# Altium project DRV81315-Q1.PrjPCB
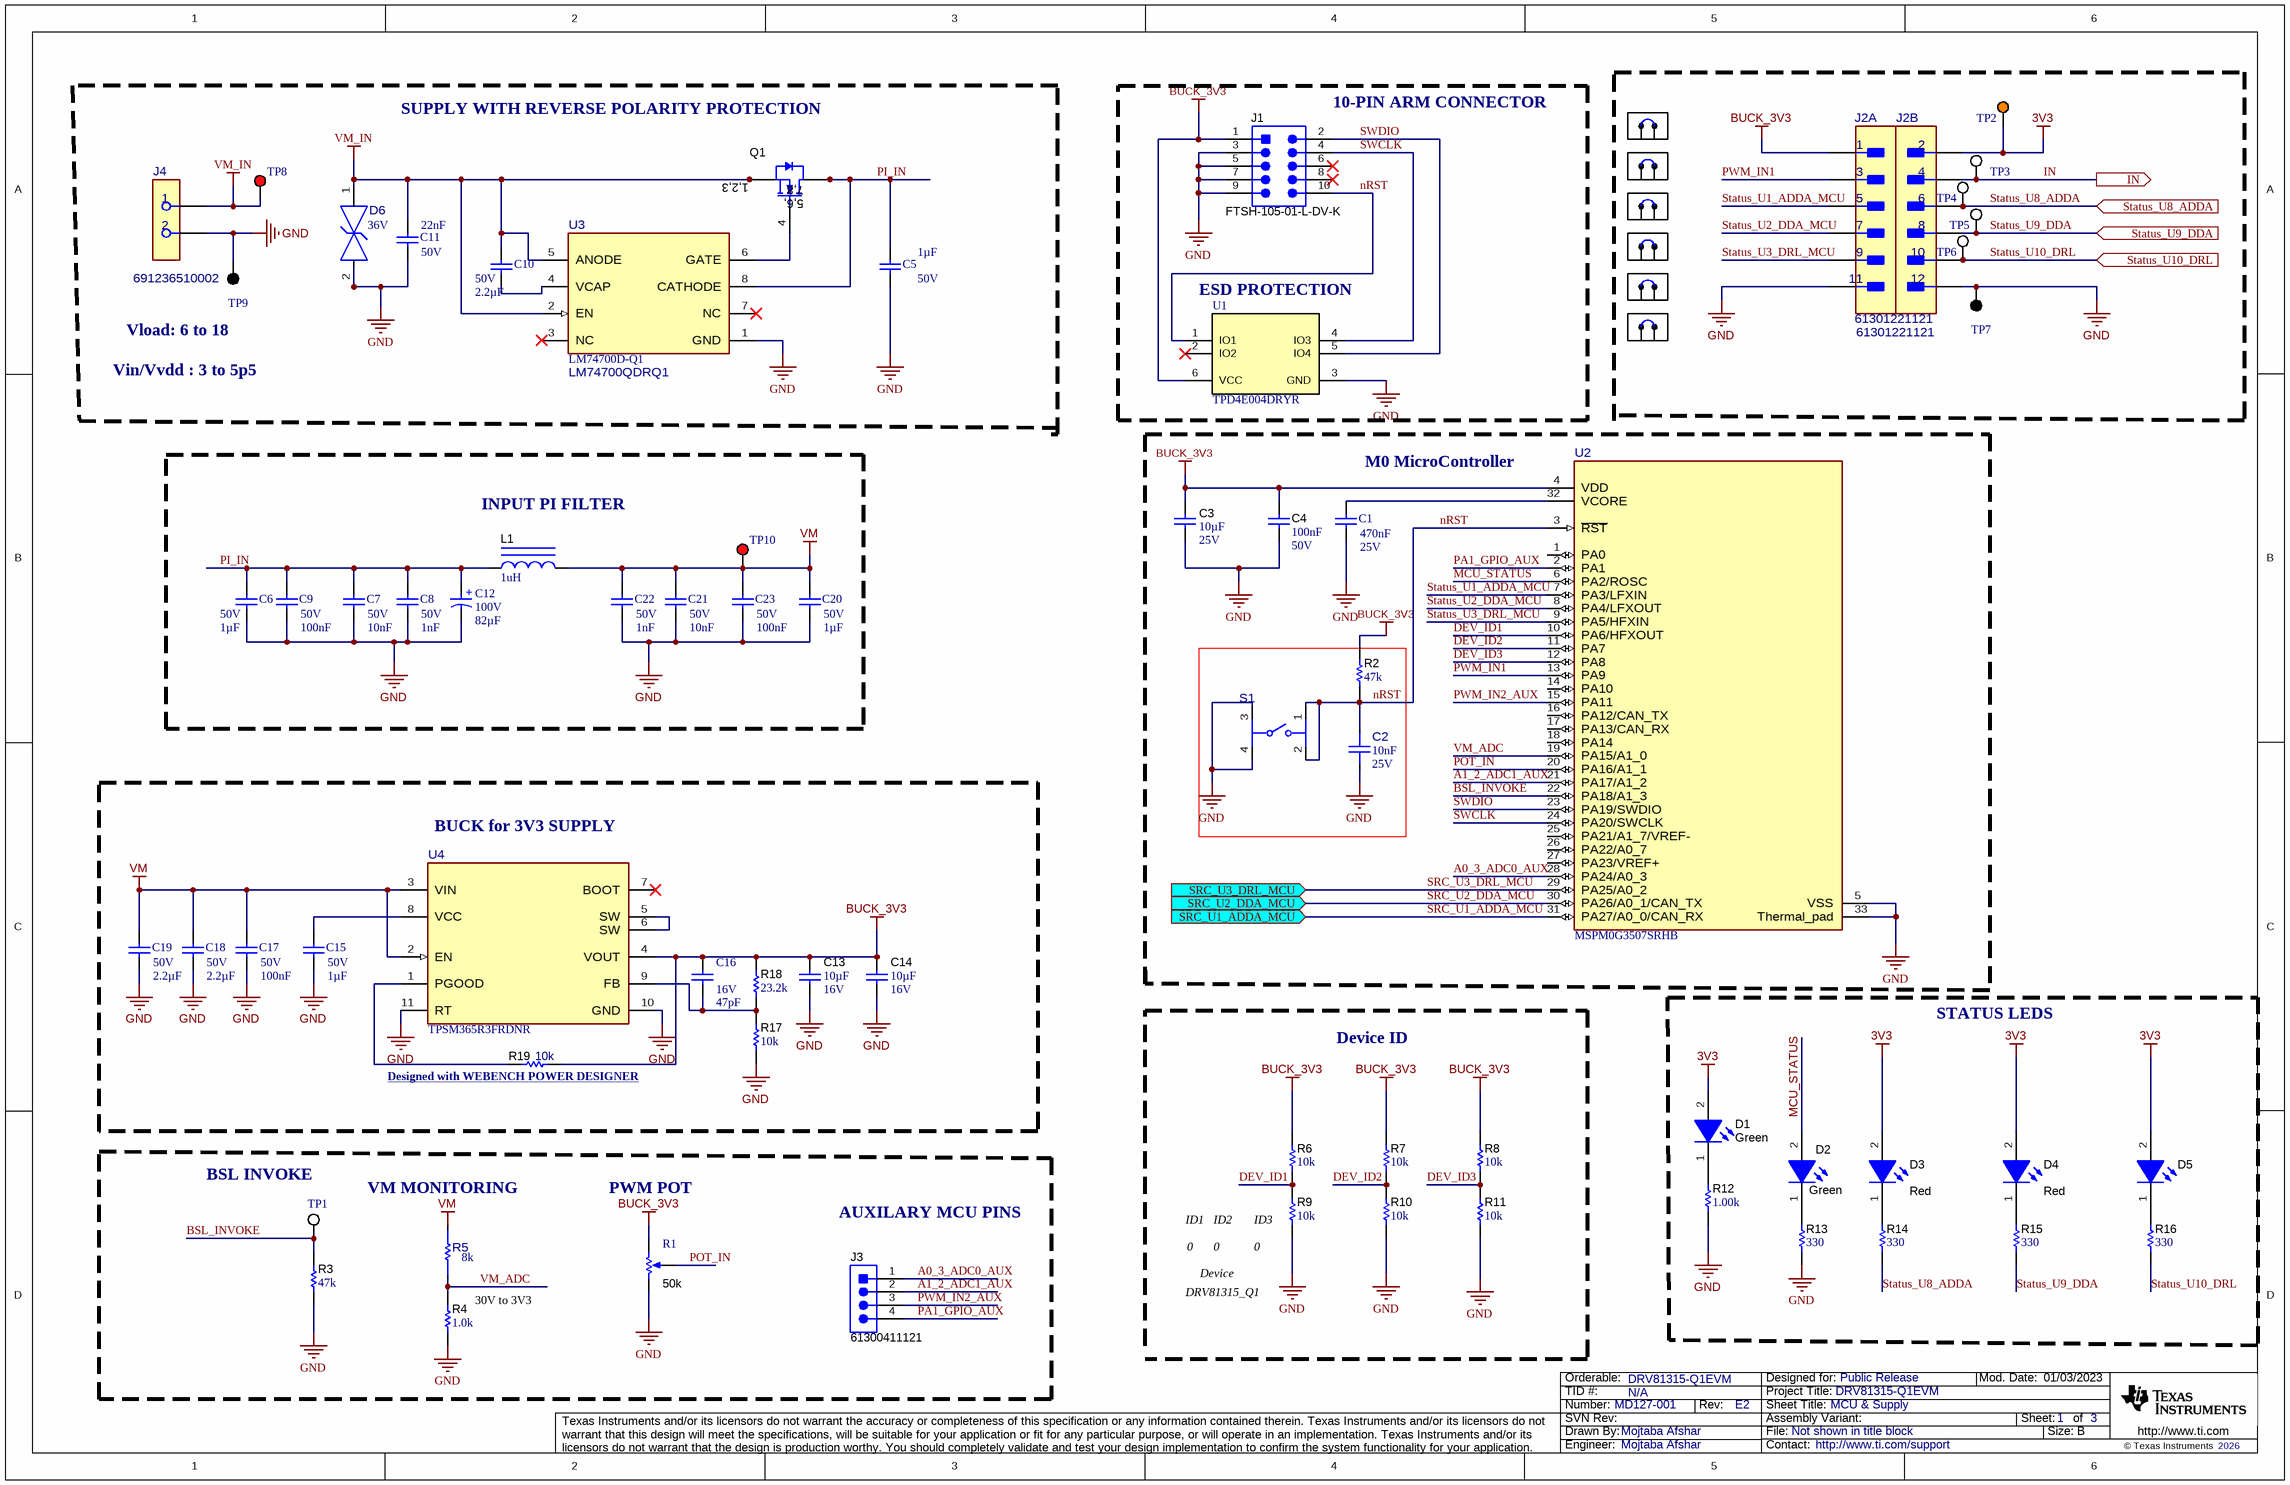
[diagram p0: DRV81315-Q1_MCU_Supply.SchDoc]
CopyrightYear: 2026; EVM_Orderable: DRV81315-Q1EVM; PCB_Layout: Mojtaba Afshar; PCB_Rev: E2; PRJ_Customer: Public Release; PRJ_Engineer: Mojtaba Afshar; PRJ_Number: MD127-001; PRJ_Title: DRV81315-Q1EVM; SCH_Rev: E2; TechSupport: http://www.ti.com/support; TID: N/A
3 sheets, 153 parts. Net scope: flat (ports and power ports of the same name join across sheets).
Board file: MD127_DRV81315_031026.PcbDoc
Sheets:
  DRV81315-Q1_MCU_Supply.SchDoc
  DRV81315AQ1_ICs.SchDoc
  DRV81315-Q1_HW.SchDoc

## Sheet DRV81315-Q1_MCU_Supply.SchDoc: MCU & Supply
size 431 x 279 mm; Date: Not shown in title block; ApprovedBy: Not shown in title block; CheckedBy: Not shown in title block; Author: Not shown in title block; CompanyName: Not shown in title block; DrawnBy: Mojtaba Afshar; Engineer: Not shown in title block; Organization: Not shown in title block; Address1: Not shown in title block; Address2: Not shown in title block; Address3: Not shown in title block; Address4: Not shown in title block; DocumentNumber: 1; Revision: Use project parameter SCH_Rev; SheetNumber: 1; SheetTotal: 3; PageSetup: Record=PageOptions¦CenterHorizontal=True¦CenterVertical=True¦PrintScale=1.00¦XCorrection=1.00¦YCorrection=1.00¦PrintKind=0¦BorderSize=5000000¦LeftOffset=0¦BottomOffset=0¦Orientation=2¦PaperLength=1000¦PaperWidth=1000¦Scale=100¦PaperSource=15¦PrintQuality=600¦MediaType=1¦DitherType=10¦PaperKind=Letter¦PrintScaleMode=1

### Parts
C1  value 470nF  Rated Voltage (DC): 25V  [WCAP-CSGP_0603_L1.6W0.8H0.8_Reflow]  (hidden comment: 885012206075R)
C2  Cap_F: 10nF  VDC_V: 25V  [FP-885012206065_0603-MFG]  (hidden comment: 885012206065)
C3  Cap_F: 10µF  VDC_V: 25V  [0603]  (hidden comment: GRM188R61E106KA73D)
C4  Cap_F: 100nF  VDC_V: 50V  [0603]  (hidden comment: 885012206095)
C5  value 1µF  Rated Voltage (DC): 50V  [WCAP-CSGP_1206_L3.2W1.6H1.6]  (hidden comment: 885012208093)
C6  value 1µF  Rated Voltage (DC): 50V  [WCAP-CSGP_1206_L3.2W1.6H1.6]  (hidden comment: 885012208093)
C7  value 10nF  Rated Voltage (DC): 50V  [WCAP-CSGP_0402_L1W0.5H0.5]  (hidden comment: 885012205067)
C8  value 1nF  Rated Voltage (DC): 50V  [WCAP-CSGP_0402_L1W0.5H0.5]  (hidden comment: 885012205061)
C9  value 100nF  Rated Voltage (DC): 50V  [WCAP-CSGP_0603_L1.6W0.8H0.8_Reflow]  (hidden comment: 885012206095)
C10  value 2.2µF  Rated Voltage (DC): 50V  [WCAP-CSGP_1812_L4.5W3.2H2.5]  (hidden comment: 885012210032)
C11  value 22nF  Rated Voltage (DC): 50V  [WCAP-CSGP_0603_L1.6W0.8H0.8_Reflow]  (hidden comment: 885012206091)
C12  value 82µF  Rated Voltage (DC): 100V  [WCAP-ATUL_D10H20]  (hidden comment: 860040875004)
C13  VDC_V: 16V  ValueDisplayed: 10µF  [0805_150]  (hidden comment: 885012107014)
C14  VDC_V: 16V  ValueDisplayed: 10µF  [0805_150]  (hidden comment: 885012107014)
C15  value 1µF  Rated Voltage (DC): 50V  [WCAP-CSGP_1206_L3.2W1.6H1.6]  (hidden comment: 885012208093)
C16  value 47pF  Rated Voltage (DC): 16V  [WCAP-CSGP_0402_L1W0.5H0.5]  (hidden comment: 885012005029)
C17  value 100nF  Rated Voltage (DC): 50V  [WCAP-CSGP_0603_L1.6W0.8H0.8_Reflow]  (hidden comment: 885012206095)
C18  value 2.2µF  Rated Voltage (DC): 50V  [WCAP-CSGP_1812_L4.5W3.2H2.5]  (hidden comment: 885012210032)
C19  value 2.2µF  Rated Voltage (DC): 50V  [WCAP-CSGP_1812_L4.5W3.2H2.5]  (hidden comment: 885012210032)
C20  value 1µF  Rated Voltage (DC): 50V  [WCAP-CSGP_1206_L3.2W1.6H1.6]  (hidden comment: 885012208093)
C21  value 10nF  Rated Voltage (DC): 50V  [WCAP-CSGP_0402_L1W0.5H0.5]  (hidden comment: 885012205067)
C22  value 1nF  Rated Voltage (DC): 50V  [WCAP-CSGP_0402_L1W0.5H0.5]  (hidden comment: 885012205061)
C23  value 100nF  Rated Voltage (DC): 50V  [WCAP-CSGP_0603_L1.6W0.8H0.8_Reflow]  (hidden comment: 885012206095)
D1  value Green  [WL-SMCW_GREEN]  (hidden comment: 150060VS75000)
D2  value Green  [WL-SMCW_GREEN]  (hidden comment: 150060VS75000)
D3  value Red  [WL-SMCW_RED]  (hidden comment: 150060RS75000)
D4  value Red  [WL-SMCW_RED]  (hidden comment: 150060RS75000)
D5  150060RS75000  [WL-SMCW_RED]  (value not drawn)
D6  VRWM: 36V  [FP-SMBJ36CA-13-F_SMB-MFG]  (hidden comment: SMBJ36CA-13-F)
J1  FTSH-105-01-L-DV-K  [Samtec_FTSH-105-01-x-DV-K]
J2  61301221121  [FP-61301221121_HDR12-MFG]  (parts A,B of 2)
J3  61300411121  [WURTH_61300411121]
J4  691236510002  [FP-691236510002_HHR2-MFG]
L1  ValueDisplayed: 1uH  [WE-LHMI_1335]  (hidden comment: 74437377010)
Q1  CSD19502Q5B  [DNK0008A]  (value not drawn)
R1  value 50k  [Bourns_3352T]  (hidden comment: 3352T-1-503LF)
R2  ValueDisplayed: 47k  [0402]  (hidden comment: CRCW040247K0JNED)
R3  ValueDisplayed: 47k  [0402]  (hidden comment: CRCW040247K0JNED)
R4  ValueDisplayed: 1.0k  [0603]  (hidden comment: RC0603JR-071KL)
R5  value 8k  [FP-RT0603BRE078KL_0603-MFG]  (hidden comment: RT0603BRE078KL)
R6  ValueDisplayed: 10k  [0603L]  (hidden comment: RC0603JR-0710KL)
R7  ValueDisplayed: 10k  [0603L]  (hidden comment: RC0603JR-0710KL)
R8  ValueDisplayed: 10k  [0603L]  (hidden comment: RC0603JR-0710KL)
R9  ValueDisplayed: 10k  [0603L]  (hidden comment: RC0603JR-0710KL)
R10  ValueDisplayed: 10k  [0603L]  (hidden comment: RC0603JR-0710KL)
R11  ValueDisplayed: 10k  [0603L]  (hidden comment: RC0603JR-0710KL)
R12  ValueDisplayed: 1.00k  [0603]  (hidden comment: RC0603FR-071KL)
R13  ValueDisplayed: 330  [0603]  (hidden comment: RC0603JR-07330RL)
R14  ValueDisplayed: 330  [0603]  (hidden comment: RC0603JR-07330RL)
R15  ValueDisplayed: 330  [0603]  (hidden comment: RC0603JR-07330RL)
R16  ValueDisplayed: 330  [0603]  (hidden comment: RC0603JR-07330RL)
R17  ValueDisplayed: 10k  [0603L]  (hidden comment: RC0603JR-0710KL)
R18  ValueDisplayed: 23.2k  [0603]  (hidden comment: RC0603FR-0723K2L)
R19  ValueDisplayed: 10k  [0603L]  (hidden comment: RC0603JR-0710KL)
S1  430481025816  [FP-430481025816_SMT_SW_6MM2_6MM2-MFG]  (value not drawn)
SH1-J2  60900213421  [Wurth_60900213421]  (value not drawn)
SH2-J2  60900213421  [Wurth_60900213421]  (value not drawn)
SH3-J2  60900213421  [Wurth_60900213421]  (value not drawn)
SH4-J2  60900213421  [Wurth_60900213421]  (value not drawn)
SH5-J2  60900213421  [Wurth_60900213421]  (value not drawn)
SH6-J2  60900213421  [Wurth_60900213421]  (value not drawn)
TP1  5002  [Keystone5002]  (value not drawn)
TP2  5013  [Keystone5013]  (value not drawn)
TP3  5012  [Keystone5012]  (value not drawn)
TP4  5012  [Keystone5012]  (value not drawn)
TP5  5012  [Keystone5012]  (value not drawn)
TP6  5012  [Keystone5012]  (value not drawn)
TP7  5011  [Keystone5011]  (value not drawn)
TP8  5010  [Keystone5010]  (value not drawn)
TP9  5011  [Keystone5011]  (value not drawn)
TP10  5010  [Keystone5010]  (value not drawn)
U1  TPD4E004DRYR  [DRY0006A]
U2  MSPM0G3507SRHB  [RHB0032E-MFG]
U3  LM74700QDRQ1  PartNumber: LM74700D-Q1  [D0008A-MFG]
U4  TPSM365R3FRDNR  [RDN0011A-MFG]

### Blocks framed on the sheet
INPUT PI FILTER: C6-C9 C12 C20-C23 L1 TP10
BUCK for 3V3 SUPPLY: C13-C19 R17-R19 U4
STATUS LEDS: D1-D5 R12-R16

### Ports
IN (out), SRC_U1_ADDA_MCU (in), SRC_U2_DDA_MCU (in), SRC_U3_DRL_MCU (in), Status_U8_ADDA (in), Status_U9_DDA (in), Status_U10_DRL (in)

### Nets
3V3: D1.2(A) D3.2(A) D4.2(A) D5.2(A) J2.2 TP2.1
BUCK_3V3: C3.1 C4.1 C13.1 C14.1 C16.2 J1.1 J2.1 R1.1(CCW) R2.2 R6.1 R7.1 R8.1 R18.2 R19.2 U1.6(VCC) U2.4(VDD) U4.4(VOUT)
GND: C1.1 C2.2 C3.2 C4.2 C5.1 C6.1 C7.1 C8.1 C9.1 C11.1 C12.2(N) C13.2 C14.2 C15.1 C17.1 C18.1 C19.1 C20.1 C21.1 C22.1 C23.1 D6.2 J1.3 J1.5 J1.7 J1.9 J2.11 J2.12 J4.2 R1.3(CW) R3.1 R4.1 R9.2 R10.2 R11.2 R12.1 R13.1 R17.1 S1.3 S1.4 TP7.1 TP9.1 U1.3(GND) U2.5(VSS) U2.33(Thermal_pad) U3.1(GND) U4.10(GND) U4.11(RT)
VM: C17.2 C18.2 C19.2 C20.2 C21.2 C22.2 C23.2 L1.2 R5.2 TP10.1 U4.2(EN) U4.3(VIN)
VM_IN: C10.2 C11.2 D6.1 J4.1 Q1.1(S) Q1.2(S) Q1.3(S) TP8.1 U3.2(EN) U3.5(ANODE)
A0_3_ADC0_AUX: J3.1 U2.28(PA24/A0_3)
A1_2_ADC1_AUX: J3.2 U2.21(PA17/A1_2)
BSL_INVOKE: R3.2 TP1.1 U2.22(PA18/A1_3)
DEV_ID1: R6.2 R9.1 U2.10(PA6/HFXOUT)
DEV_ID2: R7.2 R10.1 U2.11(PA7)
DEV_ID3: R8.2 R11.1 U2.12(PA8)
IN: J2.4 TP3.1 ; port IN
MCU_STATUS: D2.2(A) U2.6(PA2/ROSC)
nRST: C2.1 J1.10 R2.1 S1.1 S1.2 U1.1(IO1) U2.3(~{RST})
PA1_GPIO_AUX: J3.4 U2.2(PA1)
PI_IN: C5.2 C6.2 C7.2 C8.2 C9.2 C12.1(P) L1.1 Q1.5(D) Q1.6(D) Q1.7(D) Q1.8(D) Q1.9(D) U3.8(CATHODE)
POT_IN: R1.2(WIPER) U2.20(PA16/A1_1)
PWM_IN1: J2.3 U2.13(PA9)
PWM_IN2_AUX: J3.3 U2.15(PA11)
SRC_U1_ADDA_MCU: U2.31(PA27/A0_0/CAN_RX) ; port SRC_U1_ADDA_MCU
SRC_U2_DDA_MCU: U2.30(PA26/A0_1/CAN_TX) ; port SRC_U2_DDA_MCU
SRC_U3_DRL_MCU: U2.29(PA25/A0_2) ; port SRC_U3_DRL_MCU
Status_U1_ADDA_MCU: J2.5 U2.7(PA3/LFXIN)
Status_U2_DDA_MCU: J2.7 U2.8(PA4/LFXOUT)
Status_U3_DRL_MCU: J2.9 U2.9(PA5/HFXIN)
Status_U8_ADDA: J2.6 R14.1 TP4.1 ; port Status_U8_ADDA
Status_U9_DDA: J2.8 R15.1 TP5.1 ; port Status_U9_DDA
Status_U10_DRL: J2.10 R16.1 TP6.1 ; port Status_U10_DRL
SWCLK: J1.4 U1.4(IO3) U2.24(PA20/SWCLK)
SWDIO: J1.2 U1.5(IO4) U2.23(PA19/SWDIO)
VM_ADC: R4.2 R5.1 U2.19(PA15/A1_0)
NetC1_2: C1.2 U2.32(VCORE)
NetC10_1: C10.1 U3.4(VCAP)
NetC15_2: C15.2 U4.8(VCC)
NetC16_1: C16.1 R17.2 R18.1 U4.9(FB)
NetD1_1: D1.1(K) R12.2
NetD2_1: D2.1(K) R13.2
NetD3_1: D3.1(K) R14.2
NetD4_1: D4.1(K) R15.2
NetD5_1: D5.1(K) R16.2
NetQ1_4: Q1.4(G) U3.6(GATE)
NetR19_1: R19.1 U4.1(PGOOD)
NetU4_5: U4.5(SW) U4.6(SW)

Not connected (* = marked no-connect by the designer): J1 6* 8*; U1 2(IO2)*; U2 1(PA0) 14(PA10) 16(PA12/CAN_TX) 17(PA13/CAN_RX) 18(PA14) 25(PA21/A1_7/VREF-) 26(PA22/A0_7) 27(PA23/VREF+); U3 3(NC)* 7(NC)*; U4 7(BOOT)*

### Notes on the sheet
- SUPPLY WITH REVERSE POLARITY PROTECTION
- (near J1) 10-PIN ARM CONNECTOR
- (near U1) ESD PROTECTION
- (near TP9) Vload: 6 to 18
- Vin/Vvdd : 3 to 5p5
- M0 MicroController
- Device ID
- (near R19) Designed with WEBENCH POWER DESIGNER <https://webench.ti.com/power-designer/switching-regulator/customize/4?VinMin=4.5&VinMax=65&O1V=3.3&O1I=0.3&base_pn=TPSM365R3F&AppType=None&Flavor=None&op_TA=30&origin=pf_panel&lang_chosen=en-US&optfactor=3&Topology=Buck&flavor=None&VoltageOption=None>
- (near TP1) BSL INVOKE
- (near R5) VM MONITORING
- PWM POT
- AUXILARY MCU PINS
- ID1
- ID2
- (near R9) ID3
- 30V to 3V3
- DRV81315_Q1
- 0
- Device
- (near R9) 0

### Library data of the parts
C1 = CMP-0119380-1: WCAP-CSGP Multilayer Ceramic Chip Capacitor, General Purpose, size 0603, X7R Class II, 470nF, 25VDC; Manufacturer: Wurth Elektronik; Capacitance Tolerance: +/-10%; Case/Size Code: 0603; Dissipation Factor: 10%; Insulation Resistance: 1.1GOhm; Technical Reference: X7R0603474K025DFCT20000
C2 = CMP-0120893-1: 10000 pF ±10% 25V Ceramic Capacitor X7R 0603 (1608 Metric); Manufacturer: Wurth Electronics; AEC Qualified: No; SizeZ_mm: 0.87mm; TempCo: 15%; Value: 10nF
C3 = CMP-0860569-1: CAP, CERM, 10 µF, 25 V,+/- 10%, X5R, 0603; Manufacturer: MuRata; TaMin_C: -55°C; Polarized: N; SizeAreaWB_mm2: 4.68; U/M: EA; Value: 10uF; TaMax_C: 85°C; SizeZ_mm: 1; SizeX_mm: 1.6; SizeY_mm: 0.8; SizeArea_mm2: 1.28; AEC Category: Q200
C4 = CMP-0006837-4: CAP, CERM, 0.1 uF, 50 V, +/- 10%, X7R, 0603; Manufacturer: Wurth Elektronik; TaMin_C: -55°C; Polarized: N; SizeAreaWB_mm2: 4.68; Value1: Unknown; U/M: EA; Value: 0.1uF; TaMax_C: 125°C; SizeZ_mm: 1; SizeX_mm: 1.6; SizeY_mm: 0.8; SizeArea_mm2: 1.28; AEC Category: Q200
C5 C6 C15 C20 = CMP-0119636-1: WCAP-CSGP Multilayer Ceramic Chip Capacitor, General Purpose, size 1206, X7R, 1µF, 50VDC; Manufacturer: Wurth Elektronik; Capacitance Tolerance: +/-10%; Case/Size Code: 1206; Dissipation Factor: 3%; Insulation Resistance: 0.5GOhm; Technical Reference: X7R1206105K050DFCT10000
C7 C21 = CMP-0119297-1: WCAP-CSGP Multilayer Ceramic Chip Capacitor, General Purpose, size 0402, X7R, 10nF, 50VDC; Manufacturer: Wurth Elektronik; Capacitance Tolerance: +/-10%; Case/Size Code: 0402; Dissipation Factor: 2.5%; Insulation Resistance: 10GOhm; Technical Reference: X7R0402103K050DFCT10000
C8 C22 = CMP-0119291-1: WCAP-CSGP Multilayer Ceramic Chip Capacitor, General Purpose, size 0402, X7R, 1nF, 50VDC; Manufacturer: Wurth Elektronik; Capacitance Tolerance: +/-10%; Case/Size Code: 0402; Dissipation Factor: 2.5%; Insulation Resistance: 10GOhm; Technical Reference: X7R0402102K050DFCT10000
C9 C17 C23 = CMP-0119402-1: WCAP-CSGP Multilayer Ceramic Chip Capacitor, General Purpose, size 0603, X7R, 100nF, 50VDC; Manufacturer: Wurth Elektronik; Capacitance Tolerance: +/-10%; Case/Size Code: 0603; Dissipation Factor: 3%; Insulation Resistance: 5GOhm; Technical Reference: X7R0603104K050DFCT10000
C10 C18 C19 = CMP-0119739-1: WCAP-CSGP Multilayer Ceramic Chip Capacitor, General Purpose, size 1812, X7R, 2.2µF, 50VDC; Manufacturer: Wurth Elektronik; Capacitance Tolerance: +/-10%; Case/Size Code: 1812; Dissipation Factor: 2.5%; Insulation Resistance: 0.2GOhm; Technical Reference: X7R1812225K050DFCT10000
C11 = CMP-0119398-1: WCAP-CSGP Multilayer Ceramic Chip Capacitor, General Purpose, size 0603, X7R, 22nF, 50VDC; Manufacturer: Wurth Elektronik; Capacitance Tolerance: +/-10%; Case/Size Code: 0603; Dissipation Factor: 2.5%; Insulation Resistance: 10GOhm; Technical Reference: X7R0603223K050DFCT10000
C12 = CMP-0102582-1: WCAP-ATUL Aluminum Electrolytic Capacitor, Radial, THT, D10 x H20mm, 82µF, 100V; Manufacturer: Wurth Elektronik; Capacitance Tolerance: 20%; Dissipation Factor: 9%; Endurance: 7000h; Leakage Current: 82uA; Ripple Current: 600mA; Technical Reference: ATDF200820M100DSPAAG000
C13 C14 = CMP-0078154-1: CAP, CERM, 10 µF, 16 V,+/- 20%, X5R, 0805; Manufacturer: Wurth Elektronik; TaMin_C: -55°C; Polarized: N; SizeAreaWB_mm2: 6.75; U/M: EA; Value: 10uF; TaMax_C: 85°C; SizeZ_mm: 1.5; SizeX_mm: 2; SizeY_mm: 1.25; Cap_Case: 0805; SizeArea_mm2: 2.5; AEC Category: Q200
C16 = CMP-0050226-1: WCAP-CSGP Multilayer Ceramic Chip Capacitor, General Purpose, size 0402, NP0, 47pF, 16VDC; Manufacturer: Wurth Elektronik; Capacitance Tolerance: +/-5%; Insulation Resistance: 10GOhm; Q Factor: 1000; Technical Reference: NP00402470J016DFCT10000; Case/Size Code: 0402
D1 D2 = CMP-0002894-2: LED, Green, SMD; Manufacturer: Wurth Elektronik; Type: AlInGaP; Value2: 2V; Io_A: 20mA; Value1: W
D3-D5 = CMP-0002947-3: LED, Red, SMD; Manufacturer: Wurth Elektronik; Value1: 0.072W; Vf_V: 2V; Angle: 140; Tjmax_C: 85°C; Type: AlInGaP; Vr_V: 5V; Io_A: 30mA; Power_TotalModule: 72mW
D6 = CMP-0098087-1: 58.1V Clamp 10.3A Ipp Tvs Diode Surface Mount SMB; Manufacturer: Diodes Inc; AEC Qualified: No; Standoff Height: 0.05mm; TJmax_C: +150°C; Direction: Bidirectional; Breakdown Voltage: 40V; SizeZ_mm: 2.5mm; Ppk: 600W; Number Of Channels: 1
J1 = CMP-0075634-2: Header(Shrouded), 1.27mm, 5x2, Gold, SMT; Manufacturer: Samtec; Pitch_mm: 1.27; Gender: Male; Cert_CSA: Y; Current_A: 3.3A; Row_Count: 2
J2 = CMP-0092423-1: THT Vertical Pin Header WR-PHD, Pitch 2.54 mm, Dual Row, 12 pins; Manufacturer: Wurth Electronics; Is Female: no; DUT-Pitch_mm: 2.54mm; Row_Count: 2; Current_A: 3A; Voltage_V: 250V; Conn Gender: Male; Conn Orientation: Straight; SizeZ_mm: 8.89mm; ContactFinish: Gold
J3 = CMP-0054798-2: Header, 2.54 mm, 4x1, Gold, TH; Manufacturer: Wurth Elektronik; Pitch_mm: 2.54; Gender: Male; Row_Count: 1; Cert_UL: Y; Shrouded: N
J4 = CMP-0121282-1: 2 Position Wire to Board Terminal Block Horizontal with Board 0.200" (5.08mm) Through Hole; Manufacturer: Wurth Electronics; Current_A: 20A; Row_Count: 1; Voltage_V: 300V; AEC Qualified: No; Conn Gender: Female; Is Female: yes; Max Wire Gauge: 12; Min Wire Gauge: 30; SizeZ_mm: 18.1mm
L1 = CMP-0064132-1: Inductor, Shielded Drum Core, Powdered Iron, 1 uH, 15 A, 0.0027 ohm, SMD; Manufacturer: Wurth Elektronik; Isat: 26A @ 20% inductance drop; Irms: 15A @ 40C rise; Green_Lifecycle: Active; SizeAreaWB_mm2: 226.3; DCR_ohm: 2.7m; Green_REACh: Passed; Value: 1uH; Imax_A: 15A; SizeZ_mm: 3.5; SizeX_mm: 13.5; SizeY_mm: 12.6; SizeArea_mm2: 170.1; Ind_H: 1µH; AEC Category: Q200
Q1 = CMP-0000915-2: MOSFET, N-CH, 80 V, 100 A, DNK0008A (VSON-CLIP-8); Alternate Manufacturer: None; Manufacturer: Texas Instruments; SizeZ_mm: 1; ChType: N; Value2: 48 nC; VdsMax_V: 80V; SizeX_mm: 6; SizeY_mm: 5; Vgs_V: 20V; Value: 80V; SizeArea_mm2: 30; AEC Category: Q101; IdsMax_A: 100A; SizeAreaWB_mm2: 56; U/M: EA; QgTyp_nC: 48
R1 = CMP-0001777-2: Trimming Potentiometer, 50K, 0.5W, TH; Manufacturer: Bourns; CompType: Trimmer
R2 R3 = CMP-0026935-3: RES, 47 k, 5%, 0.063 W, AEC-Q200 Grade 0, 0402; Manufacturer: Vishay-Dale; Power_W: 63mW; TempCo: 200 ppm/C; Value_Code: 47k0; Value: 47k; EIA_Code: E24; SizeX_mm: 1; SizeY_mm: 0.5; SizeZ_mm: 0.6; Value2: 0.063W; AEC Qualified: Y; VDC_V: 50V; AEC Category: Q200; AEC Grade: 0
R4 = CMP-0025899-5: RES, 1.0 k, 5%, 0.1 W, 0603; Manufacturer: Yageo; Power_W: 100mW; TempCo: 100 ppm/C; Value_Code: 1k00; Value: 1.0k; EIA_Code: E24; Res_ohm: 1k; SizeX_mm: 1.6; SizeY_mm: 0.8; SizeZ_mm: 1; Value2: 0.1W; SizeArea_mm2: 1.28; AEC Qualified: N; VDC_V: 75V; AEC Category: Q200; SizeAreaWB_mm2: 4.68
R5 = CMP-0122747-1: 8 kOhms ±0.1% 0.1W, 1/10W Chip Resistor 0603 (1608 Metric) Thin Film; Manufacturer: Yageo; AEC Qualified: No; Power_W: 100mW; SizeZ_mm: 0.55mm; TempCo: 50ppm/°C; VDC_V: 75V
R6-R11 R17 = CMP-0025886-5: RES, 10 k, 5%, 0.1 W, 0603; Manufacturer: Yageo; Power_W: 100mW; TempCo: 100 ppm/C; Value_Code: 10k0; Value: 10k; EIA_Code: E24; SizeX_mm: 1.6; SizeY_mm: 0.8; SizeZ_mm: 1; Value2: 0.1W; SizeArea_mm2: 1.28; AEC Qualified: N; VDC_V: 75V; AEC Category: Q200; SizeAreaWB_mm2: 4.68
R12 = CMP-0022895-5: RES, 1.00 k, 1%, 0.1 W, 0603; Manufacturer: Yageo; Power_W: 100mW; TempCo: 100 ppm/C; Value_Code: 1k00; Value: 1.00k; EIA_Code: E96; Res_ohm: 1k; SizeX_mm: 1.6; SizeY_mm: 0.8; SizeZ_mm: 1; Value2: 0.1W; SizeArea_mm2: 1.28; AEC Qualified: N; VDC_V: 75V; AEC Category: Q200; SizeAreaWB_mm2: 4.68
R13-R16 = CMP-0025912-5: RES, 330, 5%, 0.1 W, 0603; Manufacturer: Yageo; Power_W: 100mW; TempCo: 100 ppm/C; Value_Code: 330R; Value: 330; EIA_Code: E24; SizeX_mm: 1.6; SizeY_mm: 0.8; SizeZ_mm: 1; Value2: 0.1W; SizeArea_mm2: 1.28; AEC Qualified: N; VDC_V: 75V; AEC Category: Q200; SizeAreaWB_mm2: 4.68
R18 = CMP-0022933-5: RES, 23.2 k, 1%, 0.1 W, 0603; Manufacturer: Yageo; Power_W: 100mW; TempCo: 100 ppm/C; Value_Code: 23k2; Value: 23.2k; EIA_Code: E96; SizeX_mm: 1.6; SizeY_mm: 0.8; SizeZ_mm: 1; Value2: 0.1W; SizeArea_mm2: 1.28; AEC Qualified: N; VDC_V: 75V; AEC Category: Q200; SizeAreaWB_mm2: 4.68
R19 = CMP-0025886-3: RES, 10 k, 5%, 0.1 W, 0603; Manufacturer: Yageo; Power_W: 100mW; TempCo: 100 ppm/C; Value_Code: 10k0; U/M: EA; Value: 10k; EIA_Code: E24; SizeX_mm: 1.6; SizeY_mm: 0.8; SizeZ_mm: 1; Value2: 0.1W; SizeArea_mm2: 1.28; VDC_V: 50V; AEC Category: Q200
S1 = CMP-0097347-1: Tactile Switch SPST-NO Top Actuated Surface Mount; Manufacturer: Wurth Electronics; VDC_V: 12V; Electromechanical Life: 1000000Cycles; SizeZ_mm: 2.7mm; Coil Resistance_ohm: 100mΩ; Operating Force: 160gf; AEC Qualified: No; Contact Current Rating: 50mA
SH1-J2 SH2-J2 SH3-J2 SH4-J2 SH5-J2 SH6-J2 = CMP-0003761-2: Shunt, 2.54mm, Gold, Black; Manufacturer: Wurth Elektronik
TP1 = CMP-0055139-2: Test Point, Miniature, White, TH; Manufacturer: Keystone Electronics; ContactFinish: Silver; Green_REACh: Passed; CT: TRUE; Green_Lifecycle: Active; CNHeader: FALSE
TP2 = CMP-0055150-1: Test Point, Multipurpose, Orange, TH; Manufacturer: Keystone; CNHeader: FALSE; Green_Lifecycle: Active; Green_REACh: Passed; ContactFinish: Silver; CT: TRUE
TP3-TP6 = CMP-0055149-2: Test Point, Multipurpose, White, TH; Manufacturer: Keystone Electronics; ContactFinish: Silver; CT: TRUE; CNHeader: FALSE; Green_Lifecycle: Active; Green_REACh: Passed
TP7 = CMP-0055148-2: Test Point, Multipurpose, Black, TH; Manufacturer: Keystone Electronics; CNHeader: FALSE; ContactFinish: Silver; Green_REACh: Passed; Green_Lifecycle: Active; CT: TRUE
TP8 TP10 = CMP-0055147-2: Test Point, Multipurpose, Red, TH; Manufacturer: Keystone Electronics; CNHeader: FALSE; Green_Lifecycle: Active; Green_REACh: Passed; ContactFinish: Silver; CT: TRUE
TP9 = CMP-0055148-2: Test Point, Multipurpose, Black, TH; Manufacturer: Keystone Electronics; CNHeader: FALSE; Green_Lifecycle: Active; Green_REACh: Passed; ContactFinish: Silver; CT: TRUE
U1 = CMP-0043115-2: ESD-Protection Array for High-Speed Data Interfaces, 4 Channels, -40 to +85 degC, 6-pin SON (DRY), Green (RoHS & no Sb/Br); Manufacturer: Texas Instruments; IO Leakage Current(nA): 1; USB High Speed: TRUE; IO Capacitance(Typ)(pF): 1.6; SubFamily: ESD Solution; IEC 61000-4-2 Contact(+/- kV): 8; Breakdown Voltage(Min)(V): 6; IEC 61000-4-2 Air-Gap(+/- kV): 12; AEC Category: Q200; AEC Qualified: N; CompType: IC; SizeAreaWB_mm2: 4.9; SizeArea_mm2: 1.45; SizeX_mm: 1.0; SizeZ_mm: 0.6
U2 = CMP-0093963-1: Mixed-Signal Microcontrollers with CAN-FD Interface, VQFN32; Manufacturer: Texas Instruments; TaMin_C: -40°C; Interface: I2C,SPI,UART,CAN,LIN,IrDA,SMBus; Number Of Cores: 1; Number Of Pwm Channels: 16; Data Bus Width: 32bits; Frequency_Fixed: 80MHz; Core Architecture: ARM Cortex-M0+; Number Of Timers/Counters: 7; Number Of Adc Channels: 10; Number Of Uart Channels: 4; Standoff Height: 0mm; Ram Size: 32KBytes; Number Of A/D Converters: 2; SizeZ_mm: 1mm; AEC Qualified: No; TaMax_C: +125°C; Memory Size: 128KBytes; TJmax_C: +130°C; Min Supply Voltage: 1.62V; Max Supply Voltage: 3.6V; Memory Type: FLASH; Number Of I/Os: 28
U3 = CMP-0125797-1: Manufacturer: Texas Instruments; SizeZ_mm: 1.75mm; Standoff Height: 0.11mm
U4 = CMP-0094617-1: 3-V to 65-V Input, 1-V to 13-V Output, 600-mA Synchronous Buck Converter Power Module in a HotRod QFN Package; Manufacturer: Texas Instruments; SizeZ_mm: 2.1mm; AEC Qualified: No; Max Duty Cycle: 98%; Max Supply Voltage: 65V; Min Supply Voltage: 3.6V; Nominal Supply Current: 17-18uA; Number Of Outputs: 1; Output Type: AdjustableProgrammable; Output Voltage: 1-13V; Standoff Height: 0mm; Switching Frequency: 200-2200kHz; TJmax_C: +125°C

## Sheet DRV81315AQ1_ICs.SchDoc: MSPM0G3507-Q1
size 431 x 279 mm; Date: Not shown in title block; ApprovedBy: Not shown in title block; CheckedBy: Not shown in title block; Author: Not shown in title block; CompanyName: Not shown in title block; DrawnBy: Mojtaba Afshar; Engineer: Not shown in title block; Organization: Not shown in title block; Address1: Not shown in title block; Address2: Not shown in title block; Address3: Not shown in title block; Address4: Not shown in title block; DocumentNumber: 2; Revision: Use project parameter SCH_Rev; SheetNumber: 2; SheetTotal: 3; PageSetup: Record=PageOptions¦CenterHorizontal=True¦CenterVertical=True¦PrintScale=1.00¦XCorrection=1.00¦YCorrection=1.00¦PrintKind=0¦BorderSize=5000000¦LeftOffset=0¦BottomOffset=0¦Orientation=2¦PaperLength=1000¦PaperWidth=1000¦Scale=100¦PaperSource=15¦PrintQuality=600¦MediaType=1¦DitherType=10¦PaperKind=Letter¦PrintScaleMode=1
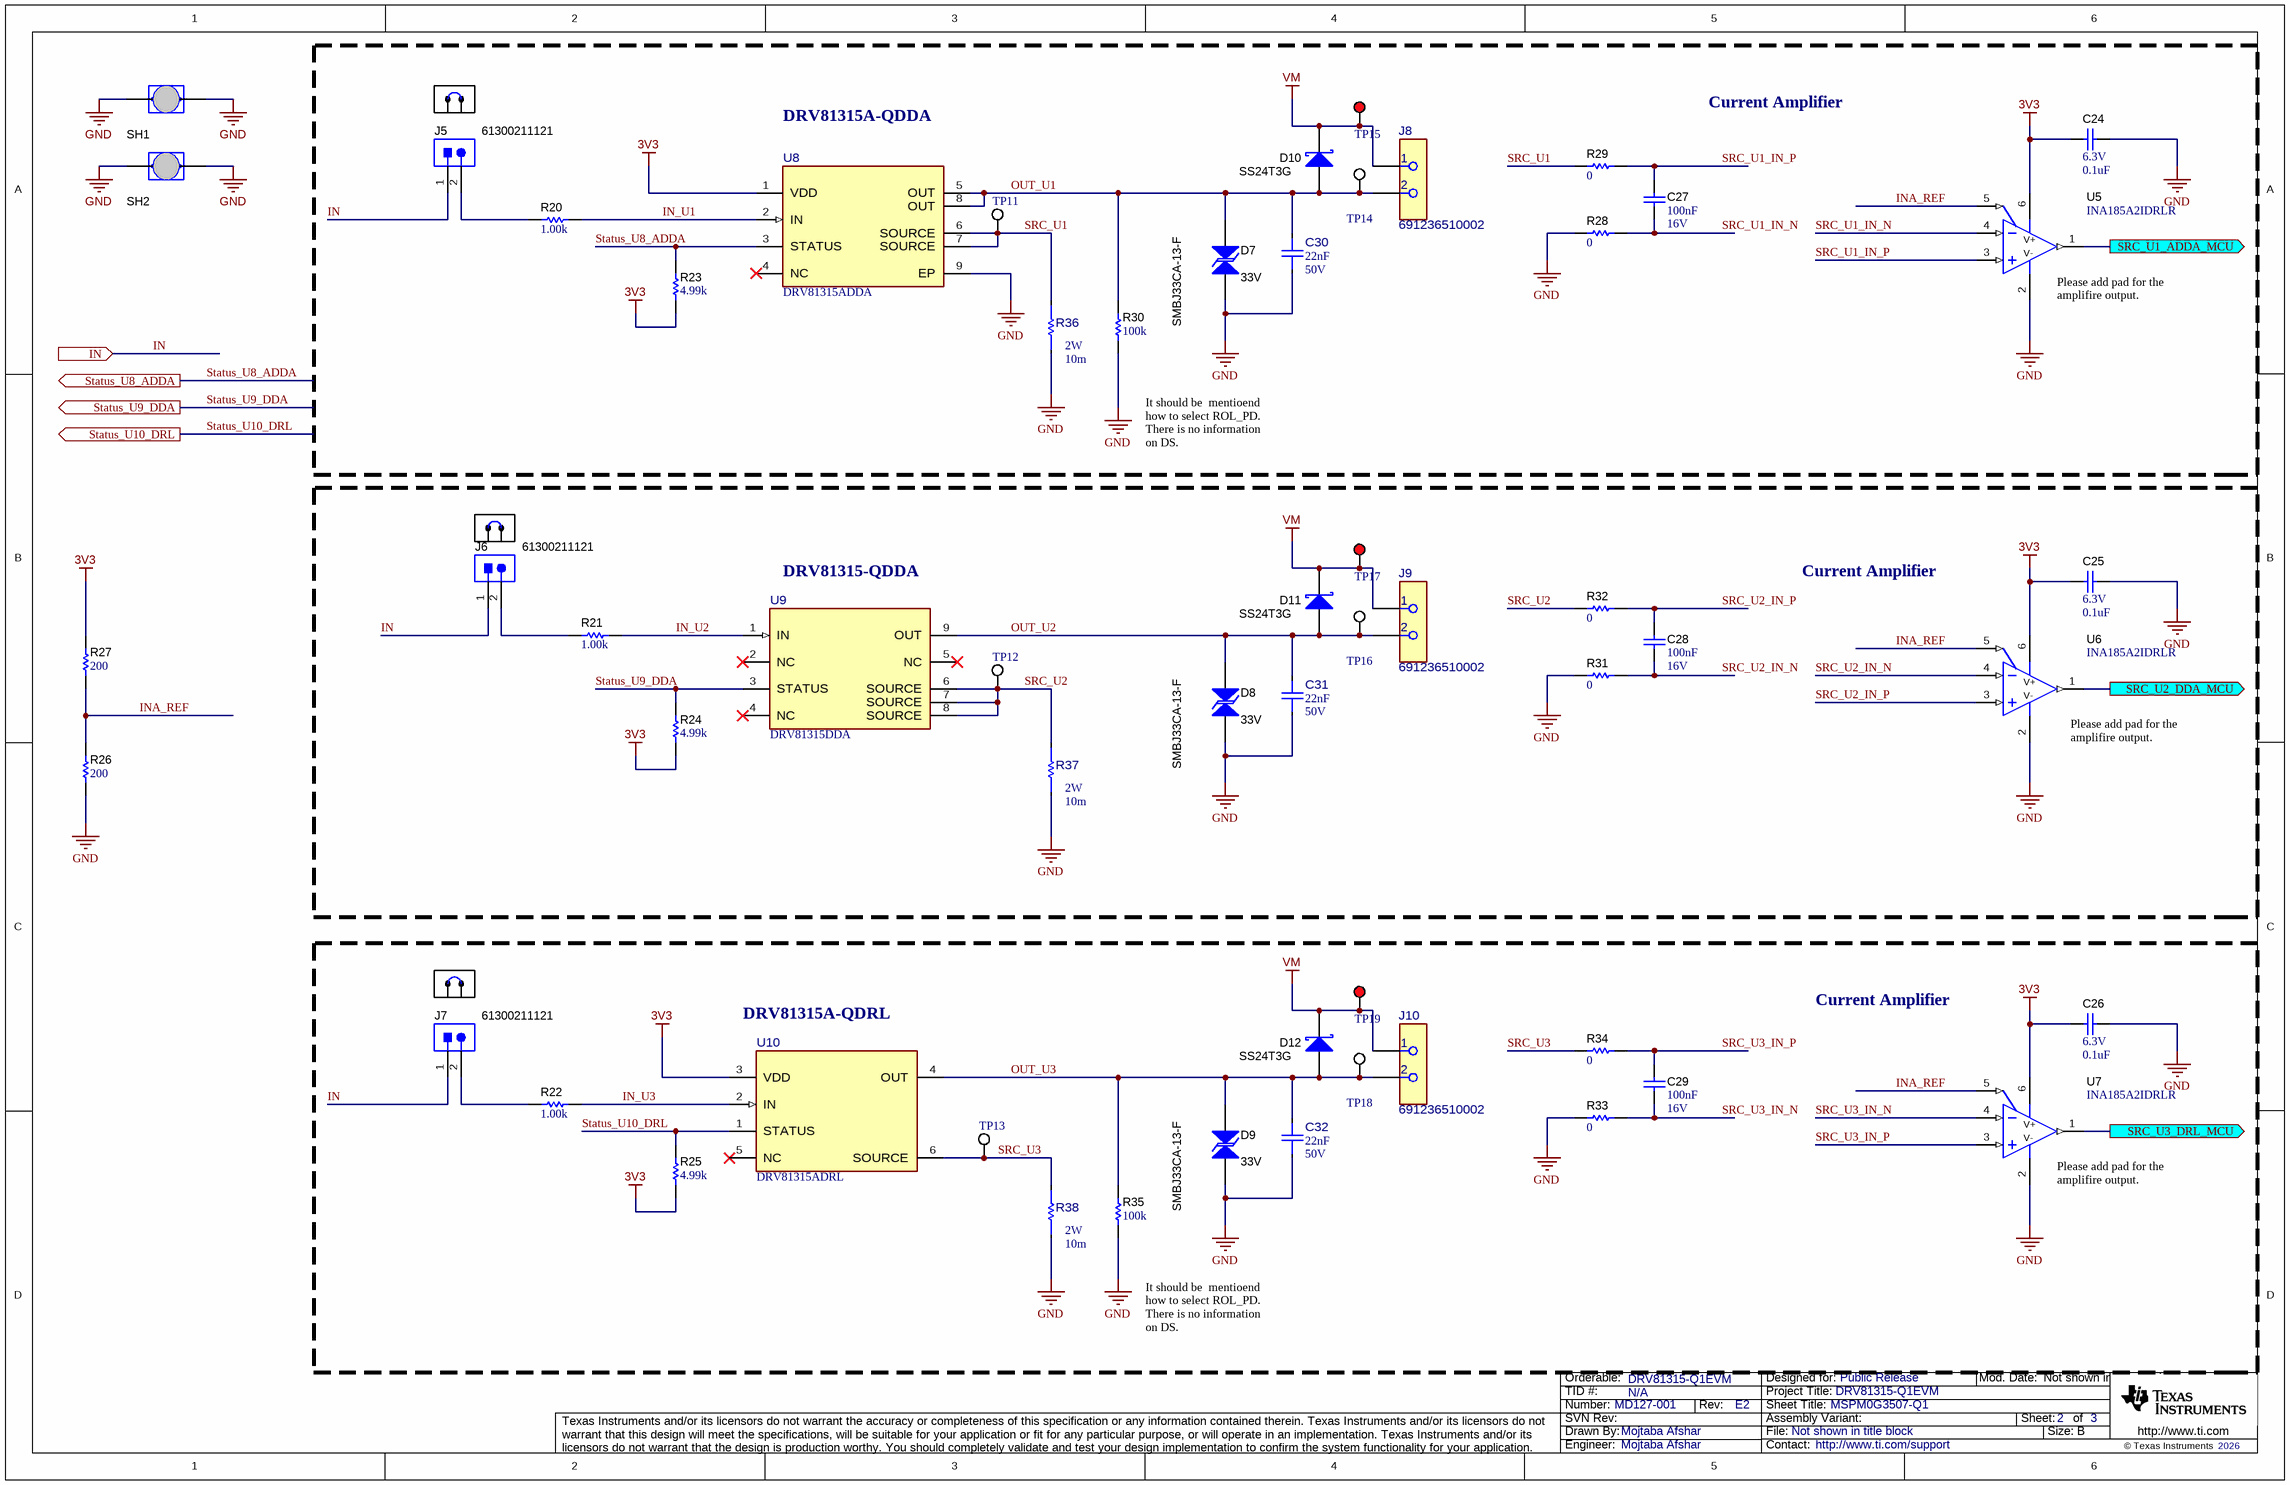
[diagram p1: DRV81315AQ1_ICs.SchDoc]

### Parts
C24  VDC_V: 6.3V  ValueDisplayed: 0.1uF  [0402]  (hidden comment: 885012105001)
C25  VDC_V: 6.3V  ValueDisplayed: 0.1uF  [0402]  (hidden comment: 885012105001)
C26  VDC_V: 6.3V  ValueDisplayed: 0.1uF  [0402]  (hidden comment: 885012105001)
C27  Cap_F: 100nF  VDC_V: 16V  [0603]  (hidden comment: 885012206046)
C28  Cap_F: 100nF  VDC_V: 16V  [0603]  (hidden comment: 885012206046)
C29  Cap_F: 100nF  VDC_V: 16V  [0603]  (hidden comment: 885012206046)
C30  Cap_F: 22nF  VDC_V: 50V  [FP-885012206091_0603-MFG]  (hidden comment: 885012206091)
C31  Cap_F: 22nF  VDC_V: 50V  [FP-885012206091_0603-MFG]  (hidden comment: 885012206091)
C32  Cap_F: 22nF  VDC_V: 50V  [FP-885012206091_0603-MFG]  (hidden comment: 885012206091)
D7  SMBJ33CA-13-F  value 33V  [SMB-Bi]
D8  SMBJ33CA-13-F  value 33V  [SMB-Bi]
D9  SMBJ33CA-13-F  value 33V  [SMB-Bi]
D10  SS24T3G  [SMB]
D11  SS24T3G  [SMB]
D12  SS24T3G  [SMB]
J5  61300211121  [WURTH_61300211121]
J6  61300211121  [WURTH_61300211121]
J7  61300211121  [WURTH_61300211121]
J8  691236510002  [FP-691236510002_HHR2-MFG]
J9  691236510002  [FP-691236510002_HHR2-MFG]
J10  691236510002  [FP-691236510002_HHR2-MFG]
R20  ValueDisplayed: 1.00k  [0603]  (hidden comment: RC0603FR-071KL)
R21  ValueDisplayed: 1.00k  [0603]  (hidden comment: RC0603FR-071KL)
R22  ValueDisplayed: 1.00k  [0603]  (hidden comment: RC0603FR-071KL)
R23  ValueDisplayed: 4.99k  [0603]  (hidden comment: RC0603FR-074K99L)
R24  ValueDisplayed: 4.99k  [0603]  (hidden comment: RC0603FR-074K99L)
R25  ValueDisplayed: 4.99k  [0603]  (hidden comment: RC0603FR-074K99L)
R26  ValueDisplayed: 200  [0603]  (hidden comment: RC0603FR-07200RL)
R27  ValueDisplayed: 200  [0603]  (hidden comment: RC0603FR-07200RL)
R28  ValueDisplayed: 0  [0603]  (hidden comment: ERJ-3GEY0R00V)
R29  ValueDisplayed: 0  [0603]  (hidden comment: ERJ-3GEY0R00V)
R30  ValueDisplayed: 100k  [0603]  (hidden comment: RC0603FR-07100KL)
R31  ValueDisplayed: 0  [0603]  (hidden comment: ERJ-3GEY0R00V)
R32  ValueDisplayed: 0  [0603]  (hidden comment: ERJ-3GEY0R00V)
R33  ValueDisplayed: 0  [0603]  (hidden comment: ERJ-3GEY0R00V)
R34  ValueDisplayed: 0  [0603]  (hidden comment: ERJ-3GEY0R00V)
R35  ValueDisplayed: 100k  [0603]  (hidden comment: RC0603FR-07100KL)
R36  Res_ohm: 10m  Power_W: 2W  [FP-PCS2512DR0100ET_2512-MFG]  (hidden comment: PCS2512DR0100ET)
R37  Res_ohm: 10m  Power_W: 2W  [FP-PCS2512DR0100ET_2512-MFG]  (hidden comment: PCS2512DR0100ET)
R38  Res_ohm: 10m  Power_W: 2W  [FP-PCS2512DR0100ET_2512-MFG]  (hidden comment: PCS2512DR0100ET)
SH1  Jumper_2p  [Harwin_D3082-05]  (value not drawn)
SH2  Jumper_2p  [Harwin_D3082-05]  (value not drawn)
SH-J5  60900213421  [Wurth_60900213421]  (value not drawn)
SH-J6  60900213421  [Wurth_60900213421]  (value not drawn)
SH-J7  60900213421  [Wurth_60900213421]  (value not drawn)
TP11  5002  [Keystone5002]  (value not drawn)
TP12  5002  [Keystone5002]  (value not drawn)
TP13  5002  [Keystone5002]  (value not drawn)
TP14  5012  [Keystone5012]  (value not drawn)
TP15  5010  [Keystone5010]  (value not drawn)
TP16  5012  [Keystone5012]  (value not drawn)
TP17  5010  [Keystone5010]  (value not drawn)
TP18  5012  [Keystone5012]  (value not drawn)
TP19  5010  [Keystone5010]  (value not drawn)
U5  INA185A2IDRLR  [DRL0006A]
U6  INA185A2IDRLR  [DRL0006A]
U7  INA185A2IDRLR  [DRL0006A]
U8  DRV81315ADDA  [DDA0008B-MFG]
U9  DRV81315DDA  [DDA0008B-MFG]
U10  DRV81315ADRL  [DRL0006A-MFG]

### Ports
IN (in), SRC_U1_ADDA_MCU (out), SRC_U2_DDA_MCU (out), SRC_U3_DRL_MCU (out), Status_U8_ADDA (out), Status_U9_DDA (out), Status_U10_DRL (out)

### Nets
3V3: C24.2 C25.2 C26.2 R23.1 R24.1 R25.1 R27.2 U5.6(V+) U6.6(V+) U7.6(V+) U8.1(VDD) U10.3(VDD)
GND: C24.1 C25.1 C26.1 C30.1 C31.1 C32.1 D7.1 D8.1 D9.1 R26.1 R28.1 R30.1 R31.1 R33.1 R35.1 R36.1 R37.1 R38.1 SH1.1 SH1.2 SH2.1 SH2.2 U5.2(V-) U6.2(V-) U7.2(V-) U8.9(EP)
VM: D10.1(K) D11.1(K) D12.1(K) J8.1 J9.1 J10.1 TP15.1 TP17.1 TP19.1
IN: J5.1 J6.1 J7.1 ; port IN
IN_U1: R20.2 U8.2(IN)
IN_U2: R21.2 U9.1(IN)
IN_U3: R22.2 U10.2(IN)
INA_REF: R26.2 R27.1 U5.5(REF) U6.5(REF) U7.5(REF)
OUT_U1: C30.2 D7.2 D10.2(A) J8.2 R30.2 TP14.1 U8.5(OUT) U8.8(OUT)
OUT_U2: C31.2 D8.2 D11.2(A) J9.2 TP16.1 U9.9(OUT)
OUT_U3: C32.2 D9.2 D12.2(A) J10.2 R35.2 TP18.1 U10.4(OUT)
SRC_U1: R29.1 R36.2 TP11.1 U8.6(SOURCE) U8.7(SOURCE)
SRC_U1_ADDA_MCU: U5.1(OUT) ; port SRC_U1_ADDA_MCU
SRC_U1_IN_N: C27.2 R28.2 U5.4(IN-)
SRC_U1_IN_P: C27.1 R29.2 U5.3(IN+)
SRC_U2: R32.1 R37.2 TP12.1 U9.6(SOURCE) U9.7(SOURCE) U9.8(SOURCE)
SRC_U2_DDA_MCU: U6.1(OUT) ; port SRC_U2_DDA_MCU
SRC_U2_IN_N: C28.2 R31.2 U6.4(IN-)
SRC_U2_IN_P: C28.1 R32.2 U6.3(IN+)
SRC_U3: R34.1 R38.2 TP13.1 U10.6(SOURCE)
SRC_U3_DRL_MCU: U7.1(OUT) ; port SRC_U3_DRL_MCU
SRC_U3_IN_N: C29.2 R33.2 U7.4(IN-)
SRC_U3_IN_P: C29.1 R34.2 U7.3(IN+)
Status_U8_ADDA: R23.2 U8.3(STATUS) ; port Status_U8_ADDA
Status_U9_DDA: R24.2 U9.3(STATUS) ; port Status_U9_DDA
Status_U10_DRL: R25.2 U10.1(STATUS) ; port Status_U10_DRL
NetJ5_2: J5.2 R20.1
NetJ6_2: J6.2 R21.1
NetJ7_2: J7.2 R22.1

Not connected (* = marked no-connect by the designer): U8 4(NC)*; U9 2(NC)* 4(NC)* 5(NC)*; U10 5(NC)*

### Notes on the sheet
- DRV81315A-QDDA
- Current Amplifier
- (near U5) Please add pad for the amplifire output.
- It should be  mentioend how to select ROL_PD. There is no information on DS.
- DRV81315-QDDA
- (near U6) Please add pad for the amplifire output.
- DRV81315A-QDRL
- (near U7) Please add pad for the amplifire output.

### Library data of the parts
C24-C26 = CMP-0006219-2: CAP, CERM, 0.1 uF, 6.3 V, +/- 20%, X5R, 0402; Manufacturer: Wurth Elektronik; TaMin_C: -55°C; Polarized: N; SizeAreaWB_mm2: 3; Value1: Unknown; U/M: EA; Value: 0.1uF; TaMax_C: 85°C; SizeZ_mm: 0.6; SizeX_mm: 1; SizeY_mm: 0.5; Cap_F: 100nF; AEC Category: Q200
C27-C29 = CMP-0006829-4: CAP, CERM, 0.1 uF, 16 V, +/- 10%, X7R, 0603; Manufacturer: Wurth Elektronik; TaMin_C: -55°C; Polarized: N; SizeAreaWB_mm2: 4.68; Value1: Unknown; U/M: EA; Value: 0.1uF; TaMax_C: 125°C; SizeZ_mm: 1; SizeX_mm: 1.6; SizeY_mm: 0.8; SizeArea_mm2: 1.28; AEC Category: Q200
C30-C32 = CMP-0120895-1: 0.022 µF ±10% 50V Ceramic Capacitor X7R 0603 (1608 Metric); Manufacturer: Wurth Electronics; AEC Qualified: No; SizeZ_mm: 0.87mm; TempCo: 15%; Value: 22nF
D7-D9 = CMP-0005564-3: Diode, TVS, Bi, 33 V, SMB; Manufacturer: Diodes Inc.; SizeX_mm: 5.6; Ppk: 600W; SizeAreaWB_mm2: 44.156; SizeZ_mm: 2.6; SizeArea_mm2: 21.336; SizeY_mm: 3.81; AEC Category: Q101
D10-D12 = CMP-0028778-2: Diode, Schottky, 40 V, 2 A, AEC-Q101, SMB; Manufacturer: ON Semiconductor; AEC Qualified: Y; Value: 40V; TJmax_C: 150°C; Value1: 2A; Green_Lifecycle: Active; Value2: 0.5V; SizeX_mm: 5.6; SizeAreaWB_mm2: 44.156; SizeY_mm: 3.81; SizeArea_mm2: 21.336; Green_REACh: Passed; SizeZ_mm: 2.6; AEC Category: Q101; Vf_V: 500mV
J5-J7 = CMP-0054794-2: Header, 2.54 mm, 2x1, Gold, TH; Manufacturer: Wurth Elektronik; Shrouded: N; Gender: Male; Green_REACh: Passed; Pitch_mm: 2.54; Green_Lifecycle: Active; Row_Count: 1; Cert_UL: Y
J8-J10 = CMP-0121282-1: as J4 on sheet DRV81315-Q1_MCU_Supply
R20-R22 = CMP-0022895-5: as R12 on sheet DRV81315-Q1_MCU_Supply
R23-R25 = CMP-0023155-5: RES, 4.99 k, 1%, 0.1 W, 0603; Manufacturer: Yageo; Power_W: 100mW; TempCo: 100 ppm/C; Value_Code: 4k99; Value: 4.99k; EIA_Code: E96; SizeX_mm: 1.6; SizeY_mm: 0.8; SizeZ_mm: 1; Value2: 0.1W; SizeArea_mm2: 1.28; AEC Qualified: N; VDC_V: 75V; AEC Category: Q200; SizeAreaWB_mm2: 4.68
R26 R27 = CMP-0022902-5: RES, 200, 1%, 0.1 W, 0603; Manufacturer: Yageo; Power_W: 100mW; TempCo: 100 ppm/C; Value_Code: 200R; Value: 200; EIA_Code: E96; SizeX_mm: 1.6; SizeY_mm: 0.8; SizeZ_mm: 1; Value2: 0.1W; SizeArea_mm2: 1.28; AEC Qualified: N; VDC_V: 75V; AEC Category: Q200; SizeAreaWB_mm2: 4.68
R28 R29 R31-R34 = CMP-0025874-4: RES, 0, 5%, 0.1 W, AEC-Q200 Grade 0, 0603; Manufacturer: Panasonic; Power_W: 100mW; TempCo: 600 ppm/C; Value_Code: 0000; Value: 0; EIA_Code: E24; SizeX_mm: 1.6; SizeY_mm: 0.8; SizeZ_mm: 1; Value2: 0.1W; SizeArea_mm2: 1.28; AEC Qualified: Y; VDC_V: 50V; AEC Category: Q200; SizeAreaWB_mm2: 4.68
R30 R35 = CMP-0022735-5: RES, 100 k, 1%, 0.1 W, 0603; Manufacturer: Yageo; Power_W: 100mW; TempCo: 100 ppm/C; Value: 100k; EIA_Code: E96; SizeX_mm: 1.6; SizeY_mm: 0.8; SizeZ_mm: 1; Value2: 0.1W; SizeArea_mm2: 1.28; AEC Qualified: N; VDC_V: 75V; AEC Category: Q200; SizeAreaWB_mm2: 4.68
R36-R38 = CMP-0088493-1: 10 mOhms ±0.5% 2W Chip Resistor 2512 (6432 Metric) Automotive AEC-Q200, Current Sense, Moisture Resistant Metal Film; Manufacturer: Ohmite; SizeZ_mm: 0.664mm; AEC Grade: Grade 0; TempCo: 50ppm/°C; AEC Qualified: Yes; Tolerance_%: 0%
SH1 SH2 = CMP-0075110-1: 1mm Uninsulated Shorting Plug, 10.16mm spacing, TH; PartNumber: D3082-05; Manufacturer: Harwin; CNHeader: False; CompType: Jumper Wire; Green_Lifecycle: Active; Green_REACh: Passed
SH-J5-SH-J7 = CMP-0003761-2: as SH1-J2 on sheet DRV81315-Q1_MCU_Supply
TP11-TP13 = CMP-0055139-2: as TP1 on sheet DRV81315-Q1_MCU_Supply
TP14 TP16 TP18 = CMP-0055149-2: as TP3 on sheet DRV81315-Q1_MCU_Supply
TP15 TP17 TP19 = CMP-0055147-2: Test Point, Multipurpose, Red, TH; Manufacturer: Keystone Electronics; CT: TRUE; ContactFinish: Silver; Green_Lifecycle: Active; CNHeader: FALSE; Green_REACh: Passed
U5-U7 = CMP-0085242-1: Bidirectional, Precision Low- and High-Side Voltage Output, Current-Sense Amplifier, DRL0006A (SOT-5X3-6); Alternate PartNumber: INA185A2IDRLT; Alternate Manufacturer: Texas Instruments; SizeY_mm: 1.6; SizeAreaWB_mm2: 6.76; AEC Category: Q200; SizeArea_mm2: 2.56; CompType: IC; AEC Qualified: N; SizeZ_mm: 0.6
U8 = CMP-0127675-1: Protected Low-Side Switch, HSOIC8; Manufacturer: Texas Instruments; SizeZ_mm: 1.7mm; AEC Qualified: Yes; AEC Grade: Grade 1; Max Supply Voltage: 5.5V; Min Supply Voltage: 3V; Nominal Supply Current: 40uA; Number Of Outputs: 1; Standoff Height: 0mm; TaMax_C: +125°C; TaMin_C: -40°C; TJmax_C: +150°C
U9 = CMP-0127704-1: Protected Low-Side Switch, HSOIC8; Manufacturer: Texas Instruments; SizeZ_mm: 1.7mm; AEC Qualified: Yes; AEC Grade: Grade 1; Max Supply Voltage: 5.5V; Min Supply Voltage: 3V; Nominal Supply Current: 40uA; Number Of Outputs: 1; Standoff Height: 0mm; TaMax_C: +125°C; TaMin_C: -40°C; TJmax_C: +150°C
U10 = CMP-0127676-1: Protected Low-Side Switch, SOT563; Manufacturer: Texas Instruments; SizeZ_mm: 0.6mm; AEC Qualified: Yes; AEC Grade: Grade 1; Max Supply Voltage: 5.5V; Min Supply Voltage: 3V; Nominal Supply Current: 40uA; Number Of Outputs: 1; Standoff Height: 0mm; TaMax_C: +125°C; TaMin_C: -40°C; TJmax_C: +150°C

## Sheet DRV81315-Q1_HW.SchDoc: HARDWARE
size 431 x 279 mm; Date: Not shown in title block; ApprovedBy: Not shown in title block; CheckedBy: Not shown in title block; Author: Not shown in title block; CompanyName: Not shown in title block; DrawnBy: Mojtaba Afshar; Engineer: Not shown in title block; Organization: Not shown in title block; Address1: Not shown in title block; Address2: Not shown in title block; Address3: Not shown in title block; Address4: Not shown in title block; DocumentNumber: 3; Revision: Use project parameter SCH_Rev; SheetNumber: 3; SheetTotal: 3; PageSetup: Record=PageOptions¦CenterHorizontal=True¦CenterVertical=True¦PrintScale=1.00¦XCorrection=1.00¦YCorrection=1.00¦PrintKind=0¦BorderSize=5000000¦LeftOffset=0¦BottomOffset=0¦Orientation=2¦PaperLength=1000¦PaperWidth=1000¦Scale=100¦PaperSource=15¦PrintQuality=600¦MediaType=1¦DitherType=10¦PaperKind=Letter¦PrintScaleMode=1
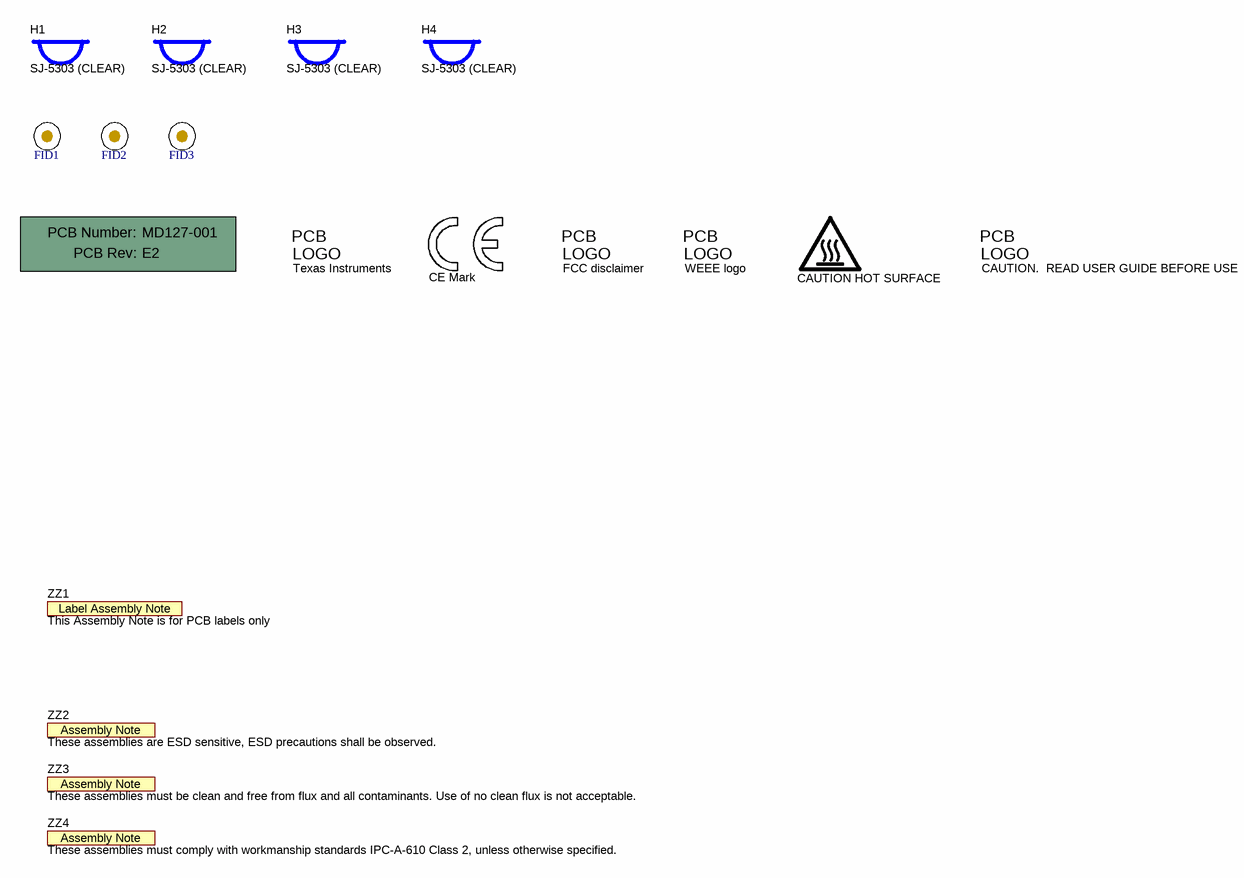
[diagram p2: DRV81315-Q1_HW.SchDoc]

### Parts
!PCB1  Printed Circuit Board  (value not drawn)  (mechanical)
FID1  Fiducial  [Fiducial10-20]  (value not drawn)
FID2  Fiducial  [Fiducial10-20]  (value not drawn)
FID3  Fiducial  [Fiducial10-20]  (value not drawn)
H1  SJ-5303 (CLEAR)  [Bumpon_SJ5003Transparent]
H2  SJ-5303 (CLEAR)  [Bumpon_SJ5003Transparent]
H3  SJ-5303 (CLEAR)  [Bumpon_SJ5003Transparent]
H4  SJ-5303 (CLEAR)  [Bumpon_SJ5003Transparent]
LOGO1  CAUTION HOT SURFACE  [IEC_HotSurface_Small]  (no BOM)
Logo2  CE Mark  [CE_Mark_5mm]  (no BOM)
Logo3  Texas Instruments  [TI_Stacked_Overlay_Small]  (no BOM)
Logo4  FCC disclaimer  [FCC_disclaimer]  (no BOM)
Logo5  WEEE logo  [WEEE_Minimum]  (no BOM)
Logo6  CAUTION.  READ USER GUIDE BEFORE USE  [IEC_Caution_Small]  (no BOM)
ZZ1  This Assembly Note is for PCB labels only  [AssemblyNoteLabel]  (no BOM)
ZZ2  These assemblies are ESD sensitive, ESD precautions shall be observed.  [AssemblyNote]  (no BOM)
ZZ3  These assemblies must be clean and free from flux and all contaminants. Use of no clean flux is not acceptable.  [AssemblyNote]  (no BOM)
ZZ4  These assemblies must comply with workmanship standards IPC-A-610 Class 2, unless otherwise specified.  [AssemblyNote]  (no BOM)

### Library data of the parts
!PCB1 = CMP-0003618-2: Manufacturer: Any; PartNumber: MD127-001
FID1-FID3 = CMP-0077181-1: Fiducial mark.  There is nothing to buy or mount.
H1-H4 = CMP-0003620-1: Bumpon, Hemisphere, 0.44 X 0.20, Clear; Manufacturer: 3M
LOGO1 = CMP-0074837-2: IEC 61010-1 Hot Surface Warning; Manufacturer: Texas Instruments; SymbolCreator: a0412235; CompType: IC; AEC Category: Q200
Logo2 = CMP-0074844-2: Manufacturer: Texas Instruments; SymbolCreator: a0412235; AEC Category: Q200; CompType: IC
Logo3 = CMP-0074838-1: Texas Instrument Corporate Signature; SymbolCreator: a0412235; Lib Reference: TI_Logo
Logo4 = CMP-0074847-1: FCC_disclaimer
Logo5 = CMP-0074769-4: Manufacturer: Texas Instruments; AEC Category: Q200; CompType: IC
Logo6 = CMP-0074836-1: IEC 61010-1 Caution Warning; SymbolCreator: a0412235; Lib Reference: IEC_Caution
ZZ1 = CMP-0003616-3
ZZ2 = CMP-0077236-1
ZZ3 = CMP-0077237-1
ZZ4 = CMP-0077238-1

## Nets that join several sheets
3V3: DRV81315-Q1_MCU_Supply (6 pins), DRV81315AQ1_ICs (12 pins)
GND: DRV81315-Q1_MCU_Supply (48 pins), DRV81315AQ1_ICs (26 pins)
VM: DRV81315-Q1_MCU_Supply (12 pins), DRV81315AQ1_ICs (9 pins)
IN: DRV81315-Q1_MCU_Supply (J2.4 TP3.1), DRV81315AQ1_ICs (J5.1 J6.1 J7.1)
SRC_U1_ADDA_MCU: DRV81315-Q1_MCU_Supply (U2.31), DRV81315AQ1_ICs (U5.1)
SRC_U2_DDA_MCU: DRV81315-Q1_MCU_Supply (U2.30), DRV81315AQ1_ICs (U6.1)
SRC_U3_DRL_MCU: DRV81315-Q1_MCU_Supply (U2.29), DRV81315AQ1_ICs (U7.1)
Status_U8_ADDA: DRV81315-Q1_MCU_Supply (J2.6 R14.1 TP4.1), DRV81315AQ1_ICs (R23.2 U8.3)
Status_U9_DDA: DRV81315-Q1_MCU_Supply (J2.8 R15.1 TP5.1), DRV81315AQ1_ICs (R24.2 U9.3)
Status_U10_DRL: DRV81315-Q1_MCU_Supply (J2.10 R16.1 TP6.1), DRV81315AQ1_ICs (R25.2 U10.1)

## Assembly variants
DRV81315-Q1EVM: not fitted C24 C25 C26 C27 C28 C29 C30 C31 C32 D6 D7 D8 D9 D10 D11 D12 J3 R6 R7 R8 R28 R29 R30 R31 R32 R33 R34 R35 U1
